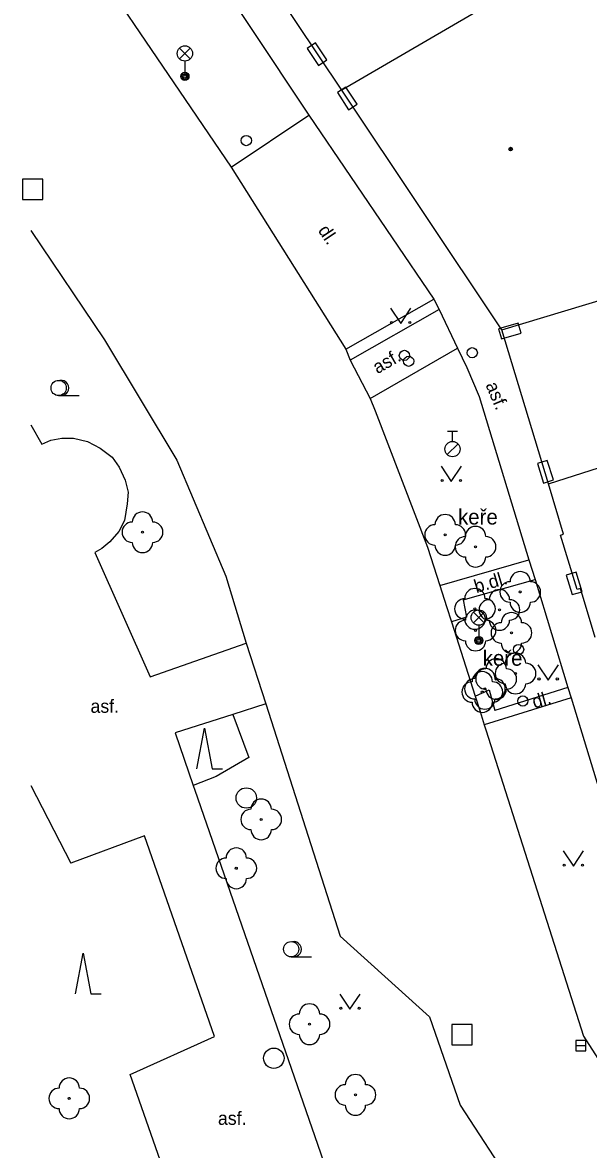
# Model space of a CAD drawing. Extents: x -595546 to -593986, y -1160845 to -1159202.
# Drawn here: x -595540 to -595512.2, y -1160208.4 to -1160153.1 of the extents above; entities that cross this region are included whole.
import ezdxf

# ---------------------------------------------------------------- set-up
doc = ezdxf.new("R2010")
doc.units = 0
for name, color, linetype in [('Level 22', 7, 'Continuous'), ('Level 24', 7, 'Continuous'), ('Level 26', 7, 'Continuous'), ('Level 27', 7, 'Continuous'), ('Level 28', 7, 'Continuous'), ('Level 33', 7, 'Continuous'), ('Level 36', 7, 'Continuous'), ('Level 39', 7, 'Continuous'), ('TM - budovy zdene_ betonove - VP', 7, 'Continuous'), ('TM - chodniky - VP', 7, 'Continuous'), ('TM - hranice souvisleho porostu (skupiny stromu_ kere)', 7, 'Continuous'), ('TM - komunikace - VP', 7, 'Continuous'), ('TM - popis povrchu', 7, 'Continuous'), ('TM - popis zelene', 7, 'Continuous'), ('TM - rozhrani mezi zpev. plochami mezi sebou - VP', 7, 'Continuous')]:
    doc.layers.add(name, color=color, linetype=linetype)

msp = doc.modelspace()

# ---------------------------------------------------------------- linework, layer by layer
at = {"layer": 'Level 22'}
for centre in [(-595534.1, -1160178.16), (-595519.26, -1160178.29), (-595517.77, -1160178.87), (-595515.58, -1160181.09), (-595517.8, -1160181.92), (-595516.6, -1160181.97), (-595517.77, -1160182.98), (-595516.01, -1160183.1), (-595515.81, -1160185.09), (-595516.76, -1160185.36), (-595517.44, -1160186), (-595517.31, -1160185.84), (-595528.28, -1160192.25), (-595529.5, -1160194.65), (-595525.91, -1160202.3), (-595537.69, -1160205.94), (-595523.66, -1160205.77)]:
    msp.add_circle(centre, 0.05, dxfattribs=at)
for centre, start, end in [((-595534.1, -1160177.66), 0, 180), ((-595519.26, -1160177.79), 0, 180), ((-595534.6, -1160178.16), 90, 270), ((-595533.6, -1160178.16), 270, 90), ((-595519.76, -1160178.29), 90, 270), ((-595518.76, -1160178.29), 270, 90), ((-595517.77, -1160178.37), 0, 180), ((-595518.27, -1160178.87), 90, 270), ((-595517.27, -1160178.87), 270, 90), ((-595534.1, -1160178.66), 180, 0), ((-595519.26, -1160178.79), 180, 0), ((-595517.77, -1160179.37), 180, 0), ((-595515.58, -1160180.59), 0, 180), ((-595516.08, -1160181.09), 90, 270), ((-595515.08, -1160181.09), 270, 90), ((-595517.8, -1160181.42), 0, 180), ((-595516.6, -1160181.47), 0, 180), ((-595518.3, -1160181.92), 90, 270), ((-595517.1, -1160181.97), 90, 270), ((-595517.3, -1160181.92), 270, 90), ((-595516.1, -1160181.97), 270, 90), ((-595515.58, -1160181.59), 180, 0), ((-595517.77, -1160182.48), 0, 180), ((-595516.01, -1160182.6), 0, 180), ((-595518.27, -1160182.98), 90, 270), ((-595517.8, -1160182.42), 180, 0), ((-595517.27, -1160182.98), 270, 90), ((-595516.6, -1160182.47), 180, 0), ((-595516.51, -1160183.1), 90, 270), ((-595515.51, -1160183.1), 270, 90), ((-595517.77, -1160183.48), 180, 0), ((-595516.01, -1160183.6), 180, 0), ((-595516.76, -1160184.86), 0, 180), ((-595515.81, -1160184.59), 0, 180), ((-595517.44, -1160185.5), 0, 180), ((-595517.31, -1160185.34), 0, 180), ((-595517.26, -1160185.36), 90, 270), ((-595516.31, -1160185.09), 90, 270), ((-595516.26, -1160185.36), 270, 90), ((-595515.31, -1160185.09), 270, 90), ((-595517.94, -1160186), 90, 270), ((-595517.81, -1160185.84), 90, 270), ((-595516.94, -1160186), 270, 90), ((-595516.81, -1160185.84), 270, 90), ((-595515.81, -1160185.59), 180, 0), ((-595516.76, -1160185.86), 180, 0), ((-595517.44, -1160186.5), 180, 0), ((-595517.31, -1160186.34), 180, 0), ((-595528.28, -1160191.75), 0, 180), ((-595528.78, -1160192.25), 90, 270), ((-595527.78, -1160192.25), 270, 90), ((-595528.28, -1160192.75), 180, 0), ((-595529.5, -1160194.15), 0, 180), ((-595530, -1160194.65), 90, 270), ((-595529, -1160194.65), 270, 90), ((-595529.5, -1160195.15), 180, 0), ((-595525.91, -1160201.8), 0, 180), ((-595526.41, -1160202.3), 90, 270), ((-595525.41, -1160202.3), 270, 90), ((-595525.91, -1160202.8), 180, 0), ((-595537.69, -1160205.44), 0, 180), ((-595523.66, -1160205.27), 0, 180), ((-595538.19, -1160205.94), 90, 270), ((-595537.19, -1160205.94), 270, 90), ((-595524.16, -1160205.77), 90, 270), ((-595523.16, -1160205.77), 270, 90), ((-595537.69, -1160206.44), 180, 0), ((-595523.66, -1160206.27), 180, 0)]:
    msp.add_arc(centre, 0.5, start, end, dxfattribs=at)
at = {"layer": 'Level 24'}
for points in [[(-595526.028, -1160154.422), (-595525.473, -1160155.254), (-595525.057, -1160154.977), (-595525.612, -1160154.145)], [(-595524.543, -1160156.586), (-595523.999, -1160157.425), (-595523.58, -1160157.153), (-595524.124, -1160156.314)], [(-595516.499, -1160168.663), (-595515.538, -1160168.386), (-595515.677, -1160167.906), (-595516.638, -1160168.183)], [(-595514.732, -1160174.789), (-595514.434, -1160175.744), (-595513.956, -1160175.594), (-595514.255, -1160174.64)], [(-595513.322, -1160180.266), (-595513.028, -1160181.222), (-595512.55, -1160181.076), (-595512.844, -1160180.12)]]:
    msp.add_lwpolyline(points, close=True, dxfattribs=at)
at = {"layer": 'Level 26'}
for points in [[(-595539.98, -1160161.83), (-595538.98, -1160161.83), (-595538.98, -1160160.83), (-595539.98, -1160160.83)], [(-595518.94, -1160203.32), (-595517.94, -1160203.32), (-595517.94, -1160202.32), (-595518.94, -1160202.32)]]:
    msp.add_lwpolyline(points, close=True, dxfattribs=at)
at = {"layer": 'Level 27'}
msp.add_line((-595512.86, -1160203.35), (-595512.36, -1160203.35), dxfattribs=at)
msp.add_lwpolyline([(-595512.86, -1160203.6), (-595512.36, -1160203.6), (-595512.36, -1160203.1), (-595512.86, -1160203.1)], close=True, dxfattribs=at)
for centre in [(-595529.01, -1160191.2), (-595527.66, -1160203.97)]:
    msp.add_circle(centre, 0.5, dxfattribs=at)
at = {"layer": 'Level 28'}
for p, q in [((-595519.15, -1160173.205), (-595518.65, -1160173.205)), ((-595518.9, -1160173.705), (-595518.9, -1160173.205)), ((-595519.158, -1160174.352), (-595518.628, -1160173.822))]:
    msp.add_line(p, q, dxfattribs=at)
for centre, radius in [((-595529.01, -1160158.94), 0.25), ((-595521.26, -1160169.48), 0.25), ((-595521.05, -1160169.77), 0.25), ((-595517.93, -1160169.35), 0.25), ((-595518.9, -1160174.08), 0.375), ((-595515.66, -1160183.91), 0.25), ((-595515.45, -1160186.44), 0.25)]:
    msp.add_circle(centre, radius, dxfattribs=at)
at = {"layer": 'Level 33'}
for p, q in [((-595532.285, -1160154.93), (-595531.755, -1160154.4)), ((-595532.285, -1160154.4), (-595531.755, -1160154.93)), ((-595532.02, -1160155.04), (-595532.02, -1160155.79)), ((-595517.875, -1160182.61), (-595517.345, -1160182.08)), ((-595517.875, -1160182.08), (-595517.345, -1160182.61)), ((-595517.61, -1160182.72), (-595517.61, -1160183.47))]:
    msp.add_line(p, q, dxfattribs=at)
for centre, radius in [((-595532.02, -1160154.665), 0.375), ((-595532.02, -1160155.79), 0.2), ((-595532.02, -1160155.79), 0.145), ((-595532.02, -1160155.79), 0.0876), ((-595517.61, -1160182.345), 0.375), ((-595517.61, -1160183.47), 0.2), ((-595517.61, -1160183.47), 0.145), ((-595517.61, -1160183.47), 0.0876)]:
    msp.add_circle(centre, radius, dxfattribs=at)
at = {"layer": 'Level 36'}
for p, q in [((-595538.21, -1160171.455), (-595537.21, -1160171.455)), ((-595526.81, -1160198.995), (-595525.81, -1160198.995))]:
    msp.add_line(p, q, dxfattribs=at)
for points in [[(-595521.94, -1160167.17), (-595521.44, -1160167.92), (-595520.94, -1160167.17)], [(-595519.46, -1160174.92), (-595518.96, -1160175.67), (-595518.46, -1160174.92)], [(-595514.71, -1160184.66), (-595514.21, -1160185.41), (-595513.71, -1160184.66)], [(-595531.429, -1160189.768), (-595531.054, -1160187.768), (-595530.679, -1160189.768), (-595530.179, -1160189.768)], [(-595513.47, -1160193.8), (-595512.97, -1160194.55), (-595512.47, -1160193.8)], [(-595537.379, -1160200.808), (-595537.004, -1160198.808), (-595536.629, -1160200.808), (-595536.129, -1160200.808)], [(-595524.43, -1160200.82), (-595523.93, -1160201.57), (-595523.43, -1160200.82)]]:
    msp.add_lwpolyline(points, dxfattribs=at)
for centre, radius in [((-595521.89, -1160167.87), 0.05), ((-595520.991, -1160167.87), 0.05), ((-595538.21, -1160171.08), 0.375), ((-595519.41, -1160175.62), 0.05), ((-595518.511, -1160175.62), 0.05), ((-595514.66, -1160185.36), 0.05), ((-595513.761, -1160185.36), 0.05), ((-595513.42, -1160194.5), 0.05), ((-595512.521, -1160194.5), 0.05), ((-595526.81, -1160198.62), 0.375), ((-595524.38, -1160201.52), 0.05), ((-595523.481, -1160201.52), 0.05)]:
    msp.add_circle(centre, radius, dxfattribs=at)
for centre in [(-595538.085, -1160171.08), (-595526.685, -1160198.62)]:
    msp.add_arc(centre, 0.375, 260.4059, 99.5941, dxfattribs=at)
at = {"layer": 'Level 39'}
for radius in [0.09, 0.0398]:
    msp.add_circle((-595516.05, -1160159.36), radius, dxfattribs=at)
at = {"layer": 'TM - budovy zdene_ betonove - VP'}
for points in [[(-595524.33, -1160156.46), (-595529.99, -1160147.97)], [(-595515.96, -1160151.57), (-595524.33, -1160156.46)], [(-595516.48, -1160168.23), (-595524.33, -1160156.46)], [(-595516.48, -1160168.23), (-595506.35, -1160165.17)], [(-595514.2, -1160175.79), (-595516.48, -1160168.23)], [(-595514.2, -1160175.79), (-595503.42, -1160172.33)], [(-595513.45, -1160178.25), (-595514.2, -1160175.79)], [(-595513.6, -1160178.3), (-595513.45, -1160178.25)], [(-595512.78, -1160180.97), (-595513.6, -1160178.3)], [(-595512.63, -1160180.92), (-595512.78, -1160180.97)], [(-595511.9, -1160183.33), (-595512.63, -1160180.92)]]:
    msp.add_lwpolyline(points, dxfattribs=at)
at = {"layer": 'TM - chodniky - VP'}
for points in [[(-595537.39, -1160140.47), (-595525.95, -1160157.7)], [(-595529.75, -1160160.25), (-595525.95, -1160157.7)], [(-595524.13, -1160169.17), (-595519.82, -1160166.72)], [(-595519.82, -1160166.72), (-595519.55, -1160167.23)], [(-595519.55, -1160167.23), (-595523.91, -1160169.72)], [(-595522.94, -1160171.6), (-595518.66, -1160169.12)], [(-595518.66, -1160169.12), (-595518.19, -1160170.07), (-595517.59, -1160171.5), (-595515.15, -1160179.51)], [(-595539.58, -1160172.894), (-595539.04, -1160173.83)], [(-595539.04, -1160173.83), (-595538.6, -1160173.64), (-595538.06, -1160173.54), (-595537.48, -1160173.54), (-595536.8, -1160173.7), (-595536.17, -1160174.03), (-595535.59, -1160174.47), (-595535.24, -1160174.97), (-595534.95, -1160175.61), (-595534.81, -1160176.19), (-595534.85, -1160176.77), (-595534.99, -1160177.58), (-595535.26, -1160178.13), (-595535.7, -1160178.63), (-595536.09, -1160178.96), (-595536.43, -1160179.16)], [(-595536.43, -1160179.16), (-595533.72, -1160185.25), (-595529.01, -1160183.61)], [(-595519.52, -1160180.78), (-595515.15, -1160179.51)], [(-595518.38, -1160181.48), (-595514.85, -1160180.48)], [(-595514.85, -1160180.48), (-595513.24, -1160185.77)], [(-595518.38, -1160181.48), (-595518.21, -1160182.33), (-595518.95, -1160182.55)], [(-595517.79, -1160186.21), (-595517.1, -1160185.89), (-595516.83, -1160186.91)], [(-595513.24, -1160185.77), (-595516.83, -1160186.91)], [(-595528.05, -1160186.58), (-595529.67, -1160187.1)], [(-595513.09, -1160186.29), (-595517.34, -1160187.61)], [(-595513.09, -1160186.29), (-595508.64, -1160200.89), (-595508.54, -1160201.79), (-595508.94, -1160202.83), (-595510.74, -1160205.59)], [(-595529.67, -1160187.1), (-595532.5, -1160188), (-595531.61, -1160190.59)], [(-595539.58, -1160190.59), (-595537.61, -1160194.39)], [(-595531.61, -1160190.59), (-595531.53, -1160190.82)], [(-595531.53, -1160190.82), (-595524.51, -1160211.12)], [(-595527.99, -1160210.32), (-595532.44, -1160211.26), (-595534.71, -1160204.77), (-595530.57, -1160202.9), (-595534, -1160193.05), (-595537.61, -1160194.39)]]:
    msp.add_lwpolyline(points, dxfattribs=at)
at = {"layer": 'TM - hranice souvisleho porostu (skupiny stromu_ kere)'}
msp.add_lwpolyline([(-595529.67, -1160187.1), (-595528.88, -1160189.22), (-595530.48, -1160190.15), (-595531.61, -1160190.59)], dxfattribs=at)
at = {"layer": 'TM - komunikace - VP'}
for points in [[(-595539.58, -1160145.768), (-595529.75, -1160160.25)], [(-595529.75, -1160160.25), (-595524.13, -1160169.17)], [(-595539.58, -1160163.356), (-595535.96, -1160168.71)], [(-595535.96, -1160168.71), (-595532.41, -1160174.62)], [(-595524.13, -1160169.17), (-595523.91, -1160169.72)], [(-595523.91, -1160169.72), (-595522.94, -1160171.6)], [(-595522.94, -1160171.6), (-595522.7, -1160172.2), (-595520.12, -1160178.89), (-595519.52, -1160180.78)], [(-595532.41, -1160174.62), (-595530.01, -1160180.31)], [(-595530.01, -1160180.31), (-595529.01, -1160183.61)], [(-595519.52, -1160180.78), (-595519.19, -1160181.81), (-595518.95, -1160182.55)], [(-595518.95, -1160182.55), (-595517.79, -1160186.21)], [(-595529.01, -1160183.61), (-595528.05, -1160186.58)], [(-595517.79, -1160186.21), (-595517.55, -1160186.95), (-595517.34, -1160187.61)], [(-595528.05, -1160186.58), (-595524.4, -1160197.98)], [(-595517.34, -1160187.61), (-595517.26, -1160187.86), (-595512.48, -1160202.89), (-595510.74, -1160205.59)], [(-595524.4, -1160197.98), (-595520.02, -1160201.94)], [(-595520.02, -1160201.94), (-595518.52, -1160206.27)], [(-595518.52, -1160206.27), (-595515.93, -1160210.27)]]:
    msp.add_lwpolyline(points, dxfattribs=at)
at = {"layer": 'TM - rozhrani mezi zpev. plochami mezi sebou - VP'}
for points in [[(-595525.95, -1160157.7), (-595519.82, -1160166.72)], [(-595519.55, -1160167.23), (-595518.66, -1160169.12)], [(-595515.15, -1160179.51), (-595514.85, -1160180.48)], [(-595513.24, -1160185.77), (-595513.09, -1160186.29)]]:
    msp.add_lwpolyline(points, dxfattribs=at)

# ---------------------------------------------------------------- texts
at = {"layer": 'TM - popis povrchu'}
for s, rotation, p in [('dl.', 304, (-595525.52, -1160163.35)), ('asf.', 30, (-595522.58, -1160170.41)), ('asf.', 292.762, (-595517.29, -1160170.93)), ('b.dl.', 16.6744, (-595517.73, -1160181.15)), ('dl.', 16, (-595514.89, -1160186.81))]:
    msp.add_text(s, height=0.65, rotation=rotation, dxfattribs=at).set_placement(p)
for p in [(-595536.65, -1160187.02), (-595530.4, -1160207.24)]:
    msp.add_text('asf.', height=0.65, dxfattribs=at).set_placement(p)
at = {"layer": 'TM - popis zelene'}
for p in [(-595518.63, -1160177.78), (-595517.42, -1160184.71)]:
    msp.add_text('keře', height=0.75, dxfattribs=at).set_placement(p)

doc.saveas('drawing.dxf')
